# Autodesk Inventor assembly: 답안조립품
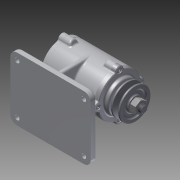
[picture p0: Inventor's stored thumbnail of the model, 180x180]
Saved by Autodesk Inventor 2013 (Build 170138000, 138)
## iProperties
Created: 2015-12
Part Number: 답안조립품
Document SubType Name: Assembly
Designer: user
Author: user
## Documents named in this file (11)
- C:\Users\user\Desktop\451208V1013\답안조립품.iam
- C:\Users\user\Desktop\451208V1013\본체.ipt
- C:\Users\user\Desktop\451208V1013\축.ipt
- C:\Users\user\Desktop\451208V1013\베어링 6204.ipt
- C:\Users\user\Desktop\451208V1013\키(4 x 4 x 12).ipt
- C:\Users\user\Desktop\451208V1013\V-벨트풀리.ipt
- C:\Users\user\Desktop\451208V1013\너트 M12x1.25.ipt
- C:\Users\user\Desktop\451208V1013\커버.ipt
- C:\Users\user\Desktop\451208V1013\커버2.ipt
- C:\Users\user\Desktop\451208V1013\오일실.ipt
- C:\Users\user\Desktop\451208V1013\볼트 M4 x 12.ipt
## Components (6 placed, 5 different names)
1. KS B 2023 6204 - 20 x 47 x 14:1
2. KS B 2023 6204 - 20 x 47 x 14:2
3. KS B 1311 (I) 4 x 4 x 12:1 — 각도:1, 각도:2
4. V-벨트풀리:1 — 각도:2
5. KS B 2804 D D - 20 32 8:1
6. KS B 1012 클래스 1 일반 - 미터 M12x1.25:1 — 각도:5
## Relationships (3: Angle 3)
- 각도:1 [Angle]: KS B 1311 (I) 4 x 4 x 12:1
- 각도:2 [Angle]: KS B 1311 (I) 4 x 4 x 12:1 ↔ V-벨트풀리:1
- 각도:5 [Angle]: KS B 1012 클래스 1 일반 - 미터 M12x1.25:1
